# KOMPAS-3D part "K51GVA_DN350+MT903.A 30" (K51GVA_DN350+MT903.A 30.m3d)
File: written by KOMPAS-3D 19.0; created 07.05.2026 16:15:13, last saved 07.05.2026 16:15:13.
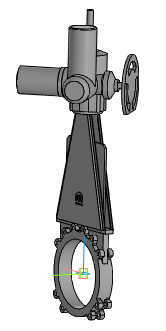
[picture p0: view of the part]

Document properties: Автор: Энергия; Полное имя файла: ..\K51GVA_DN50-DN1000+MT903.A\K51GVA_DN350+MT903.A 30.a3d

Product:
- Part/product: K51GVA_DN350+MT903.A 30
    Масса: 228.351

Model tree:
1. Операция без истории:1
